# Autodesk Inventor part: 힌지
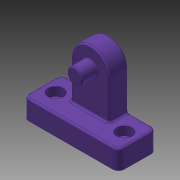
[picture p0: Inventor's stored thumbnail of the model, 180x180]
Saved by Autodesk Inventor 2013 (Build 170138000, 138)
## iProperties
Created: 2017-07
Part Number: 힌지
Material: 알루미늄 6061
Document SubType Name: Modeling
Designer: mduedu
Density: 2.71 g/cm^3
Mass: 41.2292 g
Surface Area: 53.4313 cm^2
Volume: 15.2137 cm^3
Author: mduedu
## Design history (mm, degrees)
sketch "스케치1"
  geometry: L1 (-25, 0)-(25, 0); L2 (-25, 10)-(25, 10); L3 (-25, 0)-(-25, 10); L4 (25, 0)-(25, 10); L5 (-10, 10)-(10, 10); L6 (10, 10)-(10, 40); L7 (10, 40)-(-10, 40); L8 (-10, 40)-(-10, 10); 3 further points
  constraints: 16 end point, 4 parallel, 2 horizontal, 2 midpoint, 2 perpendicular, 1 coincident, 1 point on line, 1 vertical alignment
  dimensions: "d0" = 50 distance of L1.start L1.end; "d2" = 10 distance of L1.end L2.end; "d3" = 20 distance of L6.end L7.end; "d4" = 40 distance between parallel lines of L7 L1
extrude "돌출1" new body sketch "스케치1" stored distance "d5" = 20; taper "d6" = 0 deg
extrude "돌출2" join sketch "스케치1" distance "d7" = 10; taper "d8" = 0 deg
fillet "모깎기1"
sketch "스케치2"
  geometry: C1 r 4 at (0, 30); A1 r 10 centre (0, 30) between (10, 30) and (-10, 30) reference; 1 further point
  constraints: 1 centre point, 1 coincident
  dimensions: "d9" = 8 diameter of C1
extrude "돌출3" join sketch "스케치2" distance "d10" = 8; taper "d11" = 0 deg
fillet "모깎기2" dims "d12" = 0.5
fillet "모깎기3" dims "d13" = 1
fillet "모깎기4" dims "d14" = 1
fillet "모깎기5" dims "d15" = 3
fillet "모깎기6" dims "d16" = 1
chamfer "모따기1" distance "d18" = 0.5; stored, may be unused: second distance "d19" = 2, angle "d20" = 45 deg
sketch "스케치3"
  geometry: L1 (-16, 8)-(-16, -6) reference; L2 (34, -6)-(34, 8) reference; L3 (-16, 1)-(34, 1); L4 (-13, -9)-(31, -9) reference; L5 (9, 1)-(9, -9); 2 further points
  constraints: 4 end point, 3 midpoint, 1 point on line, 1 symmetric about line
  dimensions: "d21" = 7 distance from line of point (-9, 1) L1
sketch "스케치4"
  geometry: L1 (-16, 1)-(34, 1) reference; L2 (9, 1)-(9, -9) reference; 7 further points
  constraints: 2 coincident
hole "구멍1" sketch "스케치4" at (27, 1), (-9, 1) diameter "d22" = 4.5; stored, may be unused: countersink angle "d26" = 90 deg, drill point angle "d28" = 0 deg; dims "d23" = 6, "d24" = 8, "d25" = 4.6, "d27" = 8
node "솔리드1"
